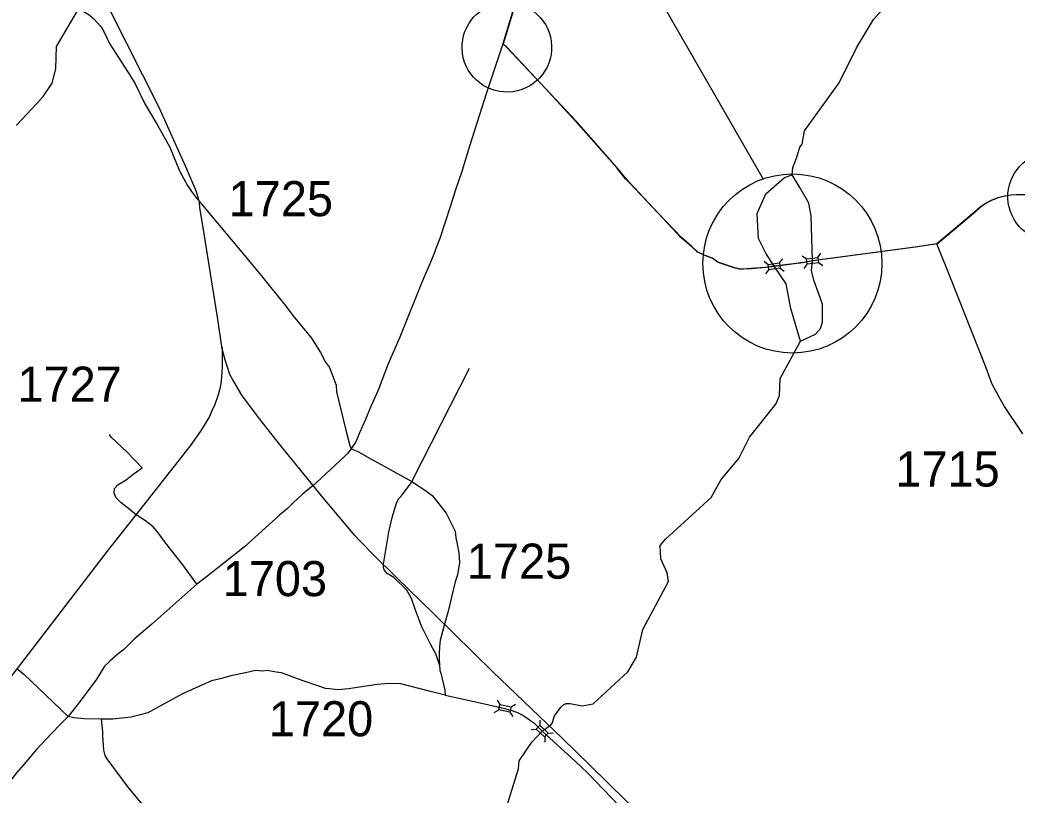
# Model space of a CAD drawing. Extents: x 0 to 2021, y 0 to 1321.
# Drawn here: x 408.2 to 541.9, y 1000.8 to 1104.7 of the extents above; entities that cross this region are included whole.
import ezdxf

# ---------------------------------------------------------------- set-up
doc = ezdxf.new("R2010")
doc.units = 0
for name, color, linetype in [('Default', 7, 'Continuous'), ('Dimension Lines', 7, 'Continuous'), ('Exist Hydro Stream or Body of Water', 7, 'Continuous'), ('Miscellaneous Lines', 7, 'Continuous'), ('Old_Level_26', 7, 'Continuous'), ('Text', 7, 'Continuous')]:
    doc.layers.add(name, color=color, linetype=linetype)

msp = doc.modelspace()

# ---------------------------------------------------------------- linework, layer by layer
at = {"layer": 'Default'}
for p, q in [((507.97, 1072.37), (508.52, 1071.94)), ((510.04, 1072.14), (510.47, 1072.69)), ((513.09, 1073.09), (513.65, 1072.67)), ((515.17, 1072.88), (515.59, 1073.44)), ((508.19, 1070.68), (508.61, 1071.23)), ((510.13, 1071.44), (510.68, 1071.01)), ((513.33, 1071.4), (513.75, 1071.96)), ((515.27, 1072.19), (515.83, 1071.77)), ((472.17, 1013.54), (472.55, 1012.95)), ((471.8, 1011.87), (472.39, 1012.25)), ((474.04, 1012.62), (474.63, 1012.99)), ((473.89, 1011.93), (474.27, 1011.35)), ((477.89, 1010.86), (477.92, 1010.16)), ((476.73, 1009.61), (477.43, 1009.64)), ((478.56, 1008.61), (478.59, 1007.91)), ((479.04, 1009.12), (479.73, 1009.15))]:
    msp.add_line(p, q, dxfattribs=at)
for points in [[(482.79, 1127.39), (481.56, 1124.85), (480.44, 1122.26), (478.8, 1118.75), (478.26, 1117.58), (478.14, 1116.96), (477.88, 1116.26), (475.76, 1110.83), (472.96, 1101.52)], [(509.34, 1071.68), (508.12, 1071.53), (506.18, 1071.37), (505.14, 1071.31), (504.58, 1071.33), (504.05, 1071.46), (501.76, 1072.22), (501.02, 1072.78), (500.24, 1073.05), (499.04, 1073.59), (498.23, 1074.33), (496.87, 1075.51), (493.78, 1078.79), (489.9, 1082.93), (489.41, 1083.42), (488.21, 1084.89), (482.75, 1091.1), (478.62, 1095.55), (473.43, 1101.07), (472.96, 1101.52)], [(531.14, 1074.7), (528.24, 1074.24), (514.47, 1072.41)], [(514.47, 1072.41), (513.29, 1072.21), (512.79, 1072.13), (512.29, 1072.07), (509.34, 1071.68)]]:
    msp.add_lwpolyline(points, dxfattribs=at)
for points in [[(513.65, 1072.67), (515.17, 1072.88), (515.27, 1072.17), (513.75, 1071.96)], [(508.52, 1071.94), (510.04, 1072.14), (510.13, 1071.43), (508.61, 1071.23)], [(472.55, 1012.95), (474.04, 1012.62), (473.89, 1011.92), (472.39, 1012.25)], [(477.92, 1010.16), (479.04, 1009.12), (478.55, 1008.6), (477.43, 1009.64)]]:
    msp.add_lwpolyline(points, close=True, dxfattribs=at)
at = {"layer": 'Dimension Lines'}
msp.add_line((507.84, 1083.41), (466.85, 1154.69), dxfattribs=at)
msp.add_ellipse((511.77, 1072.06), major_axis=(0, -12.01), ratio=0.999692, dxfattribs=at)
at = {"layer": 'Exist Hydro Stream or Body of Water'}
msp.add_line((512.77, 1082.25), (511.74, 1083.94), dxfattribs=at)
for points in [[(512.75, 1087.64), (513.08, 1088.06), (513.41, 1089.85), (518.03, 1096.27), (520.38, 1100.95), (522.64, 1104.75), (526.34, 1108.97), (531.05, 1112.63), (532.99, 1114.48), (534.58, 1117.27), (534.9, 1121.75), (535.32, 1123.04), (536.06, 1126.32), (537.49, 1128.68), (538.32, 1131.32), (538.56, 1136.31), (542.08, 1143.15), (542.58, 1144.93), (542.56, 1148.46), (541.7, 1152.76), (542.11, 1155.21), (542.09, 1161.63), (541.4, 1165.43), (541.28, 1173.28)], [(413.12, 1101.13), (416.06, 1106.16), (416.18, 1106.53), (416.09, 1107.11), (414.75, 1109.34), (413.3, 1114.22), (413.47, 1116.42), (413.8, 1117.34), (414.9, 1118.61), (417.77, 1119.98), (419.44, 1120.55)], [(410.4, 1093.45), (411.33, 1094.45), (412.52, 1096.22), (413.01, 1098.17), (413.12, 1101.13)], [(407.77, 1090.57), (407.8, 1090.64), (410.4, 1093.45)], [(511.74, 1083.94), (511.82, 1084.93), (512.32, 1086.19), (512.75, 1087.64)], [(512.85, 1061.64), (511.54, 1066.02), (510.93, 1069.33), (509.34, 1071.68), (508.21, 1073.44), (507.2, 1075.39), (507.02, 1078.75), (508.2, 1081.38), (510.72, 1083.59), (511.74, 1083.94)], [(514.66, 1069.84), (514.31, 1071.11), (514.47, 1072.41), (514.3, 1078.47), (513.95, 1080.13), (512.77, 1082.25)], [(512.85, 1061.64), (514.87, 1062.6), (515.55, 1063.35), (515.79, 1064.21), (515.78, 1066.63), (514.66, 1069.84)], [(472.46, 996.02), (475.06, 1004.31), (475.14, 1005.41), (476.82, 1007.92), (478.23, 1009.37), (479.39, 1010.22), (479.6, 1010.48), (479.84, 1011.36), (480.73, 1012.57), (481.12, 1012.93), (481.45, 1013.09), (481.99, 1013.1), (483.56, 1012.78), (485.07, 1013.02), (489.71, 1017.34), (490.88, 1019.28), (491.73, 1023.02), (495.16, 1029.43), (494.99, 1030.6), (494.14, 1032.48), (494.05, 1034.24), (494.73, 1035.09), (500.87, 1040.68), (502.22, 1043.11), (504.57, 1045.92), (506.01, 1048.79), (509.54, 1053.2), (510.04, 1054.35), (510.12, 1056.65), (512.85, 1061.64)]]:
    msp.add_lwpolyline(points, dxfattribs=at)
at = {"layer": 'Miscellaneous Lines'}
for points in [[(482.82, 1127.37), (481.6, 1124.83), (480.47, 1122.24), (478.83, 1118.73), (478.29, 1117.55), (478.17, 1116.94), (477.92, 1116.23), (475.8, 1110.81), (473, 1101.5)], [(491.97, 997.58), (484.56, 1004.84), (480.92, 1008.38), (476.79, 1012.39), (471.61, 1017.32), (463.71, 1025.11), (458.63, 1030.03), (455.61, 1033.02), (453.75, 1034.89), (453.04, 1035.64), (452.41, 1036.4), (448.85, 1040.64), (443.18, 1047.62), (440.18, 1051.4), (437.93, 1054.42), (436.72, 1056.47), (436.34, 1057.2), (436.02, 1058.18), (435.71, 1059.16), (435.32, 1060.62), (434.67, 1064.88), (433.41, 1072.96), (432.68, 1077.44), (432.33, 1079.51), (432.25, 1080.22), (432.14, 1080.78), (432.01, 1081.22), (431.77, 1081.9), (430.45, 1085.02), (426.8, 1093.06), (418.28, 1110)], [(509.39, 1071.67), (508.17, 1071.52), (506.23, 1071.36), (505.2, 1071.3), (504.63, 1071.31), (504.11, 1071.45), (501.81, 1072.21), (501.07, 1072.77), (500.3, 1073.04), (499.09, 1073.57), (498.29, 1074.32), (496.92, 1075.49), (493.83, 1078.78), (489.94, 1082.91), (489.46, 1083.4), (488.26, 1084.87), (482.8, 1091.08), (478.66, 1095.52), (473.48, 1101.04), (473, 1101.5)], [(546.61, 1081.01), (543.19, 1081.24), (541.82, 1081.27), (541.07, 1081.23), (540.27, 1081.08), (539.68, 1080.95), (539.31, 1080.84), (538.52, 1080.53), (538.07, 1080.33), (537.64, 1080.08), (537.27, 1079.82), (536.9, 1079.55), (536.2, 1078.93), (531.14, 1074.7)], [(546.66, 1081.02), (543.24, 1081.25), (541.87, 1081.27), (541.12, 1081.23), (540.32, 1081.08), (539.73, 1080.95), (539.36, 1080.84), (538.57, 1080.53), (538.12, 1080.34), (537.69, 1080.08), (537.32, 1079.83), (536.95, 1079.55), (536.25, 1078.94), (531.2, 1074.7)], [(531.2, 1074.7), (528.29, 1074.23), (514.52, 1072.41)], [(514.52, 1072.41), (513.34, 1072.2), (512.84, 1072.12), (512.34, 1072.06), (509.39, 1071.67)], [(435.29, 1060.84), (435.29, 1058.17), (435.16, 1056.34), (435.03, 1055.43), (434.72, 1054.3), (434.33, 1053.17), (433.94, 1052.3), (433.59, 1051.56), (433.07, 1050.64), (432.41, 1049.6), (431.85, 1048.81), (431.02, 1047.64), (424.1, 1038.81), (419.88, 1033.5), (402.18, 1010.51), (398.23, 1004.97)]]:
    msp.add_lwpolyline(points, dxfattribs=at)
for centre in [(473.48, 1101.04), (546.66, 1081.02)]:
    msp.add_ellipse(centre, major_axis=(-0.81, 5.95), ratio=0.999692, dxfattribs=at)
at = {"layer": 'Old_Level_26'}
for points in [[(416.06, 1106.16), (416.83, 1105.81), (417.46, 1105.37), (418.11, 1104.84), (419.02, 1103.87), (419.38, 1103.24), (420.19, 1101.56), (423.04, 1097.17), (423.64, 1096.13), (424.96, 1093.48), (426.64, 1090.59), (428.28, 1087.66), (429.6, 1084.48), (430.19, 1083.4), (430.68, 1082.52), (431.22, 1081.69), (431.89, 1080.81), (432.13, 1080.54), (432.2, 1080.45)], [(472.96, 1101.52), (470.77, 1094.92), (468.46, 1087.78), (467.43, 1084.41), (466.59, 1081.94), (465.88, 1079.64), (464.49, 1075.43), (463.96, 1074.09), (463.76, 1073.52), (463.27, 1072.32), (462.02, 1069.41), (459.11, 1062.17), (457.58, 1058.62), (456.21, 1055.06), (455.09, 1052.59), (454.51, 1051.16), (453.72, 1049.35), (453.38, 1048.45), (453.17, 1048.05), (452.88, 1047.65), (452.6, 1047.21)], [(432.2, 1080.45), (438.79, 1072.53), (440.52, 1070.46), (443.32, 1067.02), (443.76, 1066.48), (444.79, 1065.1), (447.31, 1062.05), (448.51, 1060.13), (449.18, 1058.85), (449.71, 1058.11), (450.58, 1055.73), (450.64, 1054.86), (451.89, 1049.71), (452.43, 1047.66), (452.6, 1047.21)], [(542.68, 1049.24), (540.22, 1052.91), (539.47, 1054.14), (538.56, 1055.87), (538.31, 1056.48), (537.73, 1058.09), (532.86, 1070.37), (531.14, 1074.7)], [(460.75, 1042.85), (460.8, 1042.91), (468.49, 1058.05)], [(423.76, 1038.39), (423.63, 1038.47), (422.98, 1039.03), (421.76, 1039.97), (421.09, 1040.67), (420.81, 1041.29), (420.86, 1041.91), (421.33, 1042.37), (421.79, 1042.68), (422.56, 1043.17), (422.72, 1043.27), (423.39, 1043.81), (424.57, 1044.69), (422.56, 1046.75), (420.44, 1048.78), (420.21, 1049.13)], [(452.6, 1047.21), (452.1, 1046.61), (451.71, 1046.19), (448.57, 1043.3), (447.97, 1042.7), (447.51, 1042.29)], [(452.6, 1047.21), (453.52, 1046.85), (455.15, 1045.94), (457.04, 1044.89), (460.75, 1042.85)], [(456.94, 1031.7), (456.95, 1031.78), (457.64, 1036.04), (458.04, 1037.83), (458.44, 1039.24), (458.74, 1040.07), (459.01, 1040.55), (459.34, 1040.93), (460.64, 1042.66), (460.75, 1042.85)], [(460.75, 1042.85), (462.57, 1041.65), (463.46, 1040.95), (464.2, 1040.06), (465.35, 1038.59), (466.55, 1036.18), (466.63, 1035.3), (466.83, 1034.42), (467.03, 1033.26), (467.11, 1031.97), (466.87, 1030.33), (466.54, 1029.4), (465.58, 1025.27), (465.14, 1023.7)], [(447.51, 1042.29), (446.03, 1041.08), (444.83, 1039.99), (444.05, 1039.24), (442.98, 1038.31), (438.31, 1034.07), (433.21, 1030.07), (431.91, 1029.06)], [(431.91, 1029.06), (430.03, 1031.68), (427.59, 1034.81), (426.66, 1036.11), (426.04, 1036.76), (425.04, 1037.56), (423.76, 1038.39)], [(464.45, 1018.27), (463.98, 1019.72), (463.49, 1020.54), (463.25, 1021.02), (462.05, 1023.47), (461.17, 1025.72), (460.69, 1027.16), (460.09, 1028.28), (458.33, 1029.97), (457.43, 1030.53), (457.05, 1031.02), (456.97, 1031.19), (456.94, 1031.39), (456.94, 1031.7)], [(431.91, 1029.06), (425.89, 1023.7), (423.52, 1021.69), (422.14, 1020.31), (421.38, 1019.74), (420.28, 1018.8), (420, 1018.48), (419.53, 1018.07), (418.4, 1016.24), (415.84, 1012.8), (414.66, 1011.34)], [(465.14, 1023.7), (464.52, 1021.55), (464.44, 1020.7), (464.4, 1019.73), (464.4, 1018.96), (464.45, 1018.27)], [(407.77, 1017.78), (408.73, 1017), (414.66, 1011.34)], [(465.2, 1014.18), (463.25, 1014.69), (459.27, 1015.72), (457.66, 1015.78), (456.09, 1015.65), (452.24, 1015.06), (450.84, 1014.93), (450.44, 1014.98), (449.71, 1015.03), (449.17, 1015.1), (448.15, 1015.43), (446.02, 1016.17), (443.26, 1017.2), (442.53, 1017.28), (441.35, 1017.51), (440.76, 1017.43), (439.79, 1017.51), (438.46, 1017.21), (436.48, 1016.77), (435.05, 1016.41), (433.89, 1016.1), (430, 1014.36), (425.35, 1011.83), (424.32, 1011.55), (423.05, 1011.23), (420.63, 1010.99), (419.1, 1010.98)], [(464.45, 1018.27), (464.51, 1017.52), (464.61, 1017.17), (465.15, 1014.85), (465.2, 1014.18)], [(465.2, 1014.18), (469.48, 1013.26), (473.22, 1012.43)], [(473.22, 1012.43), (474.28, 1012.12), (475.01, 1011.85), (475.62, 1011.54), (476.35, 1011.04), (477.08, 1010.47), (478.23, 1009.37)], [(414.66, 1011.34), (413.51, 1010.2), (411.69, 1008.27), (410.43, 1006.9), (408.71, 1004.89), (407.73, 1003.79), (406.34, 1002.02), (405.86, 1001.42), (405.51, 1001.06)], [(419.1, 1010.98), (416.82, 1011.01), (415.44, 1011.14), (414.66, 1011.34)], [(419.1, 1010.98), (419.23, 1009.72), (419.27, 1009.27), (419.25, 1008.78), (419.41, 1006.81), (419.58, 1006.1), (419.84, 1005.66), (422.66, 1001.88), (426.33, 997.45), (427.4, 995.93), (428.25, 994.94), (429.58, 992.88), (430.7, 991.4), (430.82, 991.14), (430.85, 990.87), (430.85, 990.69), (430.76, 990.43), (430.64, 990.21), (430.33, 989.73)], [(478.23, 1009.37), (482.69, 1005.31), (484.29, 1003.77), (489.63, 998.27), (491.74, 995.51), (492.66, 994.6), (493.99, 993.38), (495.3, 992.28)]]:
    msp.add_lwpolyline(points, dxfattribs=at)

# ---------------------------------------------------------------- texts
at = {"layer": 'Text'}
for s, p in [('1725', (436.18, 1078.4)), ('1727', (407.86, 1053.53)), ('1715', (525.57, 1042.16)), ('1725', (468.12, 1029.81)), ('1703', (435.38, 1027.47)), ('1720', (441.57, 1008.69))]:
    msp.add_text(s, height=4.705, rotation=360, dxfattribs=at).set_placement(p)

doc.saveas('drawing.dxf')
